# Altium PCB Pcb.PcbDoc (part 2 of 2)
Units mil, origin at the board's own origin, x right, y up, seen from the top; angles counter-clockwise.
Board outline 4875.67 x 2076.77 mil, 2 copper layers (Top Layer, Bottom Layer), stack 55.6 mil thick; 76 components, 37 nets, 162 pads, 28 vias.
Unrouted connection lines stored in the file: 67.
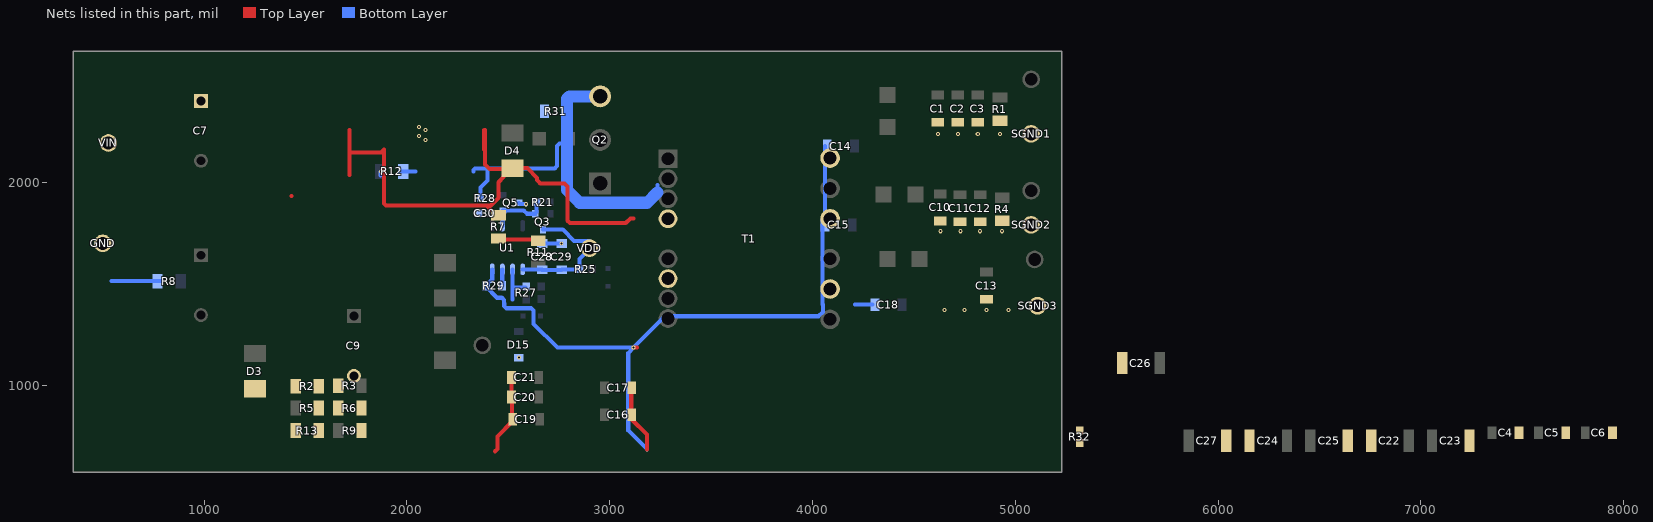
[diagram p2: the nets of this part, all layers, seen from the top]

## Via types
v1: diameter 20, hole 10, Top Layer to Bottom Layer, 28 vias

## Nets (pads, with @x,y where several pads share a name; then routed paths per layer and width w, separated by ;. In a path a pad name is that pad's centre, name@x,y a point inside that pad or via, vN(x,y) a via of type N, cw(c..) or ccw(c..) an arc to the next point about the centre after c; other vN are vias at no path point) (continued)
NetQ2_3: Q2.3 R28.2 R31.2 | length 1893.1
  Bottom Layer w20: 2327.53,2054.7 2327.53,2062.2 2335.25,2069.92 2396.32,2069.92 2728.97,2069.92 2740.69,2081.63 2740.69,2181.27 2752.4,2192.99 2778.45,2192.99 2790.1,2204.64 ; R28.2@2362.83,1923.41 2362.83,1976.56 2396.32,2010.05 2396.32,2067.95 ; 3235.04,1950.79 3235.04,1988.19
  Bottom Layer w60: Q2.3@2952.76,2425.09 2801.82,2425.09 2790.1,2413.37 2790.1,1962.53 2852.15,1900.48 3184.74,1900.48 3235.04,1950.79
NetQ3_1: Q3.1 Q5.1 R21.1 U1.6 | length 301.4
  Bottom Layer w20: U1.6@2470.73,1786.64 2470.73,1804.35 2473.29,1806.91 Q5.1@2473.29,1862.43 2576,1862.43 2592.15,1846.28 Q3.1@2633.48,1846.28 ; Q3.1@2633.48,1848.25 2639.39,1854.16 R21.1@2639.39,1903.52
NetR2_1: R2.1 R5.2
NetR6_1: R6.1 R7.2
NetR7_1: R7.1 R9.2 | length 199.9
  Top Layer w20: R7.1@2451.52,1723.88 2456.52,1718.88 2642.27,1718.88 2647.26,1713.89
NetR8_1: R8.1 R11.2 | length 244.1
  Bottom Layer w20: 542.67,1513.61 R8.1@786.77,1513.61
NetR12_1: R12.1 R13.2 | length 65
  Bottom Layer w20: R12.1@1976.38,2054.7 2041.34,2054.7
NetR27_1: R27.1 R32.2 U1.2 | length 262.3
  Bottom Layer w20: 2520.73,1481.92 R27.1@2585.1,1481.92 ; U1.2@2520.73,1572.07 2520.73,1474.21 ; 2520.73,1474.21 2520.73,1426.16 2520.73,1424.19 2520.73,1474.21
NetR29_2: R29.2 U1.3 | length 82.6
  Bottom Layer w20: R29.2@2468.17,1490.49 2470.04,1492.35 2470.04,1571.38 U1.3@2470.73,1572.07
PGND: C9.2 C22.1 C24.1 C26.1 C28.2 C29.2 C30.2 D3.2 D15.1 GND.1@500,1700 Q5.3 R13.1 R29.1 R31.1 R32.1 T1.6 U1.4 | length 3879
  Top Layer w20: 1430.29,1934.49 1431.26,1934.49 ; 3106.3,987.84 3106.3,855.41 3106.3,833.75 3183.58,756.47 3183.58,683.44 3184.06,682.97 ; v1(3118.43,1185.77) 3134.17,1185.77
  Bottom Layer w20: U1.4@2420.73,1572.07 2420.73,1521.78 2403.05,1504.11 2399.12,1504.11 2389.43,1494.42 R29.1@2389.43,1490.49 2389.43,1486.55 2444.08,1431.91 2467.74,1431.91 2479.23,1420.41 2479.23,1405.36 2479.83,1404.76 2479.83,1391.82 2491.55,1380.1 2612.8,1380.1 2624.52,1368.39 2624.52,1302.78 2741.53,1185.77 v1(3118.43,1185.77) ; Q5.3@2552.03,1899.83 2557.78,1894.08 2587.12,1894.08 v1(2588.05,1893.15) ; C28.2@2667.11,1699.44 v1(2763.13,1699.44) ; 3184.06,682.97 3184.06,685.28 3091.54,777.8 3091.54,792.56 3091.54,889.86 3091.54,987.84 3091.54,1158.88 v1(3118.43,1185.77) ; 4061.26,2180 4061.26,1802.6 4050,1791.34 4050,1398.9 4051.26,1397.64 4051.26,1362.2 4029.76,1340.71 3273.37,1340.71 v1(3118.43,1185.77)
  other v1: 2552.03,1136.32 2092.52,2209.08 2060,2229.23 2092.52,2258.27 2060,2275.02
SGND1: C1.2 C2.2 C3.2 C4.2 C5.2 C6.2 C23.2 R1.1 SGND2.1 T1.10
  other v1: 4618.38,2240 4716.81,2240 4815.23,2240 4924.75,2240
SGND2: C10.2 C11.2 C12.2 C13.2 C14.2 C15.2 C25.2 R3.1 SGND1.1 T1.12 | length 24
  Top Layer w20: C10.2@4620.62,1810.23 C10.2@4630.46,1810.23 C10.2@4632.37,1808.32 ; C11.2@4727.49,1806.4 4727.49,1804.43 C11.2@4729.45,1806.4 ; C12.2@4827.31,1806.4 C12.2@4832.08,1811.17
  other v1: 4632.37,1760 4729.45,1760 4827.31,1760 4935.58,1760
SGND3: C16.2 C17.2 C18.2 C19.2 C20.2 C21.2 C27.2 R4.1 SGND3.1 T1.14 | length 489.9
  Top Layer w20: 2435.13,674.84 2447.16,686.87 2447.16,748.34 2521.64,822.82 C19.2@2521.64,832.67 2518.91,835.4 2518.91,939.58 C20.2@2516.18,942.31 C21.2@2516.18,1039.2
  Bottom Layer w20: 4208.74,1397.64 C18.2@4296.15,1397.64
  other v1: 4652.21,1372.12 4750.63,1372.12 4858.36,1372.12 4967.07,1372.12
VDD: C28.1 C29.1 Q3.3 R25.2 U1.1 VDD.1 | length 664.9
  Bottom Layer w20: U1.1@2570.73,1572.07 2572.01,1570.8 2665.84,1570.8 C28.1@2667.11,1569.52 C29.1@2763.13,1569.52 2764.41,1570.8 2849.14,1570.8 R25.2@2850.41,1572.07 2850.41,1622.74 2900.61,1672.93 VDD.1@2900.61,1676.48 ; Q3.3@2674.32,1770.97 Q3.3@2670.89,1767.54 2768.54,1767.54 2824.95,1711.13 VDD.1@2900.61,1711.13
VIN: C7.1 D4.2 R2.2 R6.2 T1.4 VIN.1 | length 2735.7
  Top Layer w20: 1715.87,2037.04 1715.87,2147.53 ; 1715.87,2258.27 1715.87,2147.53 ; 2381.3,2260.14 2381.3,2162.3 2385.83,2157.78 ; 2385.83,2260.14 2385.83,2157.78 ; 2440.69,1838.05 2392.7,1886.05 ; D4.2@2492.62,2066.8 2407.32,2066.8 2385.83,2088.3 2385.83,2157.78 ; 3118.43,1823.56 3102.68,1823.56 3079.14,1800.02 2803.58,1800.02 2791.87,1811.74 2791.87,1980.37 2776.28,1995.96 2776.12,1995.96 2668.42,1995.96 2657.59,1995.96 2642,2011.55 2642,2022.37 2593.6,2070.77 2509.3,2070.77 2476.8,2038.27 2476.8,2026.77 2451.52,2001.49 2451.52,1924.18 2413.39,1886.05 2392.7,1886.05 ; 1715.87,2147.53 1871.05,2147.53 1885.83,2162.3 1885.83,1897.76 1897.54,1886.05 2392.7,1886.05
  Bottom Layer w20: 1870.27,2034.26 1870.27,2052.92 v1(1872.05,2054.7)
pads on no net: GND.1@2371.72,1197.49 T1.1 T1.3 T1.7 T1.8
copper on no net: | length 2532.4
  Top Layer w20: 1328.68,2147.53 1391.1,2147.53 1390.94,2147.69 1390.94,2255.18 1390.78,2255.34 ; 1505.27,2037.04 1601.7,2037.04 ; 1601.7,2147.53 1505.27,2147.53 1505.12,2147.69 1505.12,2255.18 1504.96,2255.34 1507.89,2258.27 1601.7,2258.27 ; 2520.8,2244.78 2624.83,2244.78 2652.98,2216.63 2653.38,2216.63 ; 2648.73,1323.22 2763.38,1323.22 ; 2669.53,2212.64 2668.42,2211.53 2668.42,2110.13 2776.12,2110.13 ; 2988.18,1282.93 3081.73,1282.93 3102.68,1303.88 3118.43,1303.88 3118.43,1504.67 ; 3118.43,1941.67 3118.43,2142.46 ; 4253.21,1504.67 4256.22,1504.67 ; 4253.21,1823.56 4256.22,1823.56 ; 4256.22,2142.46 4260.92,2147.16
  Bottom Layer w20: 2145.67,2054.7 2223.2,2054.7 ; 2435.13,674.84 2513.74,753.45 2513.74,807.6 2526.02,819.87 2526.02,926.91 ; 2640.19,926.91 2640.19,819.87 2646.1,813.97 2646.1,680.75 2652,674.84 ; 2966.58,682.97 2966.58,755.42 2978.29,767.13 2980.47,767.13 2991.14,777.8 2991.14,792.56 2991.14,889.86 2991.14,987.84
  other v1: 2167.32,2209.08 2197.27,2229.23 2167.32,2253.94 2196.65,2275.02

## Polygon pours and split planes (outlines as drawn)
no net on Top Layer "HV_plus" (solid, remove dead copper, pour order 17): 354.33,2598.43 777.56,2598.43 787.4,2608.27 787.4,2147.69 984.25,2147.69 984.25,2056.99 718.6,2056.99 718.5,2057.09 718.5,1934.49 358.82,1934.49 354.33,1938.98
PGND on Top Layer "Top_PGND" (solid, remove dead copper, pour order 1): 354.33,1131.65 917.55,1134.09 915.35,1958.66 2378.54,1958.66 2378.54,1909.45 3976.38,1909.45 3976.38,554.53 354.33,570.87
SGND2 on Top Layer "Sec_GND2" (solid, remove dead copper, pour order 7): 4197.44,1850.39 5230,1850.39 5230,1732.28 4197.44,1732.28
no net on Top Layer "Sec_Out2" (solid, remove dead copper, pour order 6): 4473.57,1673.23 5211.76,1673.23 5211.76,1512.57 4644.3,1534.27 4473.57,1574.8
SGND3 on Top Layer "Sec_GND3" (solid, remove dead copper, pour order 5): 4217.52,1530.6 4296.05,1531.25 4529.98,1451 5204.51,1446.77 5204.51,1338.58 4217.52,1338.58
NetC10_1 on Top Layer "Sec_Out2" (solid, remove dead copper, pour order 4): 4468.5,1998.03 5206.69,1998.03 5206.69,1899.61 4468.5,1899.61
NetC1_1 on Top Layer "Sec_Out1" (solid, remove dead copper, pour order 2): 4325.91,2627.95 5211.61,2627.95 5211.61,2390.21 4325.91,2390.21
SGND1 on Top Layer "Sec_GND1" (solid, remove dead copper, pour order 3): 4217.52,2172.24 4498.03,2214.57 4557.34,2332.37 4961.61,2332.37 5230,2321.49 5230,2113.44 4217.52,2113.44
VIN on Top Layer "HV_In" (solid, remove dead copper, pour order 0): 1340.19,2316.75 1340.51,2316.44 1340.51,1975.63 2823.11,1975.63 2823.76,1976.27 2822.38,1977.65 2822.38,2053.04 2622.16,2053.04 2584.6,2090.6 1771.26,2090.6 1766.46,2095.4 1766.46,2319.68 1343.12,2319.68
PGND on Bottom Layer "Top_PGND" (solid, remove dead copper, pour order 9): 9.84,2637.8 4090,2637.8 4090,9.84 9.84,9.84
SGND3 on Bottom Layer "Sec_GND3" (solid, remove dead copper, pour order 14): 4390,1456.69 5190,1456.69 5190,1338.58 4390,1338.58
SGND1 on Bottom Layer "Sec_GND1" (solid, remove dead copper, pour order 13): 4390,2303.15 5150,2303.15 5150,2113.44 4390,2113.44
SGND2 on Bottom Layer "Sec_GND2" (solid, remove dead copper, pour order 12): 4390,1850.39 5150,1850.39 5150,1732.28 4390,1732.28

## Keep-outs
Keep-Out Layer:
  text ".Layer_Name" at 577,-858.49 h60

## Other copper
Top Layer:
  pour cut-out: 1291.96,1973.68 1313.72,1973.68 2554.12,1973.68 2554.12,1330 1281.9,1330
  pour cut-out: 2573.68,1909.45 2573.68,1832.5 2722.27,1745.89 2745.11,1455.35 2416.09,1455.35 2416.09,1909.45
  pour cut-out: 2732.3,1940.66 2760,1750 3128.54,1682.25 3302.09,1720.36 3302.09,1936.66
  pour cut-out: 1643.7,2332.68 2868.16,2332.68 2868.16,1909.45 1634.5,1909.45
  text ".Layer_Name" at 577,-858.49 h60
Bottom Layer:
  pour cut-out: 382.96,2622.04 382.96,1122.05 836.61,1122.05 836.61,2619.27
  pour cut-out: 1690,2192.47 1690,1879.26 2432.21,1879.26 2432.21,2187.93
  pour cut-out: 2864.17,2647.64 2850.41,2633.88 2850.41,2069.92 3740,2069.92 3740,2647.64
  text ".Layer_Name" at 577,-858.49 h60

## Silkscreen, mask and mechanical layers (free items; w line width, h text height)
Top Overlay:
  text "PMP23326B" at 4644.3,610 h108.27
  text ".Layer_Name" at 577,-858.49 h60
Bottom Overlay:
  text ".Layer_Name" at 577,-858.49 h60
Top Paste:
  text ".Layer_Name" at 577,-858.49 h60
Bottom Paste:
  text ".Layer_Name" at 577,-858.49 h60
Top Solder:
  text ".Layer_Name" at 577,-858.49 h60
  text ".Layer_Name" at 577,-858.49 h60
Bottom Solder:
  text ".Layer_Name" at 577,-858.49 h60
Drill Guide:
  text ".Layer_Name" at 577,-858.49 h60
M1 Board Outline:
  lines w10: 354.33,561.02 5230,561.02 5230,1460.45 5230,1738.37 5230,2127.76 5230,2375.73 5230,2628.64 5230,2647.64 4212.6,2647.64 4049.21,2647.64 354.33,2647.64 354.33,561.02
  text ".Layer_Name" at 577,-858.49 h60
M2 Board Dimensions:
  rectangle: 0,-275 125,-150
  rectangle: 125,-400 500,-275
  lines w7: 0,-275 1000,-275 ; 125,-400 125,-150 ; 250,-400 250,-150 ; 500,-400 500,-150 ; 750,-400 750,-150 ; 0,-400 1000,-400 1000,-150 0,-150 0,-400
  text ".Layer_Name" at 577,-858.49 h60
M3 3D STEP Top:
  text ".Layer_Name" at 577,-858.49 h60
M4 3D STEP Bottom:
  text ".Layer_Name" at 577,-858.49 h60
M5 Assembly Top:
  lines w10: -292,-930.17 6308,-930.17 ; -292,-726.83 6310,-726.83 ; -292,-523.5 -292,-1133.5 3713,-1133.5 6310,-1133.5 6310,-523.5 -291.5,-523.5 -291.5,-1133.5 1284,-1133.5 ; 2173,-1133.5 2173,-523.5 ; 3440,-726.83 3440,-523.5 ; 4280,-726.83 4280,-523.5 ; 4902,-1140 4902,-937.17
  text "COMPONENTS MARKED 'DNP' SHOULD NOT BE POPULATED." at 1153.5,-318.5 h60
  text "ASSEMBLY VARIANT:" at 1153,-434 h60
  text ".VariantName" at 2189,-434 h60
  text "PCB VIEWED FROM TOP SIDE" at -228.5,-655.67 h60
  text "BOARD #:" at 2248,-655.67 h60
  text ".PRJ_Number" at 2793.5,-655.67 h60
  text "REV:" at 3638,-655.67 h60
  text ".PCB_Rev" at 3929.5,-655.67 h60
  text "SVN REV:" at 4476,-655.67 h60
  text ".VersionControl_RevNumber" at 4982,-655.67 h60
  text "TID #:" at 2248,-859 h60
  text ".TID" at 2793.5,-859 h60
  text "PLOT NAME =" at -228.5,-1064.34 h60
  text ".plot_File_Name" at 577,-1064.34 h60
  text "GENERATED    :" at 2250,-1064.34 h60
  text ".Print_Date" at 3119.5,-1064.34 h60
  text ".Print_Time" at 3848.5,-1064.34 h60
  text "TEXAS INSTRUMENTS" at 5113,-1064.34 h60
M6 Assembly Bottom:
  lines w10: -292.5,-727.33 6309.5,-727.33 ; -290.5,-930.67 6309.5,-930.67 ; 1115.5,-1140.5 1115.5,-937.67 ; 1737.5,-727.33 1737.5,-524 ; 2577.5,-727.33 2577.5,-524 ; 3844.5,-1134 3844.5,-524 ; 4733.5,-1134 6309,-1134 6309,-524 -292.5,-524 -292.5,-1134 2304.5,-1134 6309.5,-1134 6309.5,-524
  text "COMPONENTS MARKED 'DNP' SHOULD NOT BE POPULATED." at 6102,-318 h60
  text ".VariantName" at 5058,-434 h60
  text "ASSEMBLY VARIANT:" at 6097,-434 h60
  text ".VersionControl_RevNumber" at 1035.5,-656.17 h60
  text "SVN REV:" at 1541.5,-656.17 h60
  text ".PCB_Rev" at 2088,-656.17 h60
  text "REV:" at 2379.5,-656.17 h60
  text ".PRJ_Number" at 3224,-656.17 h60
  text "BOARD #:" at 3769.5,-656.17 h60
  text "PCB VIEWED FROM BOTTOM SIDE" at 6246,-656.17 h60
  text ".TID" at 3224,-859.5 h60
  text "TID #:" at 3769.5,-859.5 h60
  text "TEXAS INSTRUMENTS" at 904.5,-1064.84 h60
  text ".Print_Time" at 2169,-1064.84 h60
  text ".Print_Date" at 2898,-1064.84 h60
  text "GENERATED    :" at 3767.5,-1064.84 h60
  text ".plot_File_Name" at 5440.5,-1064.84 h60
  text "PLOT NAME =" at 6246,-1064.84 h60
M9 Title Sheet:
  drawing of 57 lines, arcs and shapes, not listed
  text "1" at 739.84,8036.5 h70
  text "2" at 3235.5,8036.5 h70
  text "3" at 5724.84,8036.5 h70
  text "4" at 8231.51,8036.5 h70
  text "5" at 10730.5,8036.5 h70
  text "6" at 13235.5,8036.5 h70
  text "A" at -416.5,6893.5 h70
  text "A" at 14383.5,6893.5 h70
  text "B" at -416.5,4513.5 h70
  text "B" at 14383.5,4513.5 h70
  text "C" at -416.5,2138.5 h70
  text "C" at 14383.5,2138.5 h70
  text "PROJECT TITLE:" at 11343.5,277.5 h45
  text ".PRJ_Title" at 11393.5,144.17 h70
  text "DESIGNED FOR:" at 11343.5,-23.5 h45
  text ".PRJ_Customer" at 11393.5,-163.5 h70
  text "D" at -416.5,-231.5 h70
  text "D" at 14383.5,-231.5 h70
  text "FILE NAME:" at 11343.5,-323.5 h45
  text ".PCB_File_Name_No_Path" at 11393.5,-443.5 h70
  text "Texas Instruments (TI) and/or its licensors do not warrant the accuracy or completeness of this specification" at 6374,-605.34 h45
  text "ENGINEER:" at 11343.5,-613.5 h45
  text "LAYOUT BY:" at 12848.5,-613.5 h45
  text "or any information contained therein. TI and/or its licensors do not warrant that this design will meet" at 6329.01,-718 h45
  text ".PRJ_Engineer" at 11393.5,-768.49 h70
  text ".PCB_Layout" at 12899,-768.49 h70
  text "the specifications, will be suitable for your application or fit for any particular purpose, or will operate in" at 6329.01,-830.67 h45
  text ".Layer_Name" at 577,-858.49 h60
  text "ALTIUM DESIGNER VERSION:" at 12848.5,-923.5 h45
  text "an implementation. TI and/or its licensors do not warrant that the design is production worthy. You should" at 6329.01,-943.33 h45
  text "completely validate and test your design implementation to confirm the system functionality for your application." at 6374,-1056 h45
  text ".print_Scale" at 11393.5,-1056.83 h70
  text ".Application_BuildNumber" at 12899,-1056.83 h70
  text "1" at 739.84,-1263.5 h70
  text "2" at 3235.5,-1263.5 h70
  text "3" at 5724.84,-1263.5 h70
  text "4" at 8231.51,-1263.5 h70
  text "5" at 10730.5,-1263.5 h70
  text "6" at 13235.5,-1263.5 h70
M10 Fab Notes:
  drawing of 189 lines, arcs and shapes, not listed
  text "DESIGN INFORMATION" at 12382.02,6356.17 h60
  text "MIN. TRACK WIDTH:" at 11737.46,6224.05 h60
  text "8" at 12833.7,6224.05 h60
  text "MIL" at 12988.46,6224.05 h60
  text "MIN. CLEARANCE:" at 11737.46,6099.92 h60
  text "0.2" at 12773.7,6099.93 h60
  text "mm" at 12988.46,6099.92 h60
  text "MIN. VIA PAD SIZE:" at 11737.46,5975.8 h60
  text "24" at 12803.71,5975.8 h60
  text "MIL" at 12988.46,5975.8 h60
  text "0.05mm (2MIL)" at 12432.46,5845.9 h60
  text "MINIMUM ANNULAR RING" at 11408.23,5837.67 h60
  text "EXTERNAL" at 13140.46,5837.67 h60
  text "PER" at 11608.23,5727.55 h60
  text "IPC-D-275 CLASS 2 LEVEL C" at 11828.23,5727.54 h60
  text "MIL, HOLES" at 13316.46,5627.07 h60
  text "+/-" at 12924,5618.48 h60
  text "+/-" at 13778,5618.48 h60
  text "REGISTRATION TOLERANCES:" at 11408.23,5617.42 h60
  text "METAL" at 12608,5617.42 h60
  text "5" at 13184.2,5617.42 h60
  text "3" at 14017.2,5617.42 h60
  text "MIL" at 14133.46,5617.42 h60
  text "HOLE SIZE TOLERANCE (UNLESS OTHERWISE SPECIFIED):" at 11408.23,5519.1 h60
  text "+/-" at 13778,5516.23 h60
  text "3" at 14017.2,5515.17 h60
  text "MIL" at 14133.46,5515.17 h60
  text "MATERIAL:" at 11333.46,5377.52 h60
  text "FR-4 High Tg" at 12319.9,5249 h60
  text "X" at 12175.46,5241.01 h60
  text "FR-408" at 11754.46,5236.49 h60
  text "OTHER" at 13242.46,5236.49 h60
  text "62 MIL (1.6mm) +/-10%" at 12074.56,5093.46 h60
  text "X" at 11954.46,5091.01 h60
  text "THICKNESS:" at 11408.23,5085.24 h60
  text "OTHER" at 13359.46,5085.24 h60
  text "TOLERANCE:" at 11408.23,4946.92 h60
  text "X" at 12256.46,4946.92 h60
  text "ANSI IPC-6012 TYPE 3 CLASS 2" at 12434.48,4946.92 h60
  text "OTHER +/-" at 12434.46,4802.73 h60
  text "BOW & TWIST:" at 11408.23,4657.54 h60
  text "X" at 12256.46,4657.54 h60
  text "ANSI IPC-6012 TYPE 3 CLASS 2" at 12434.48,4657.54 h60
  text "OTHER +/-" at 12434.46,4510.85 h60
  text "DRILLING:" at 11333.46,4380.23 h60
  text "NC_DRILL FILES" at 13094.46,4275.04 h60
  text "REFERENCE:" at 11408.23,4271.1 h60
  text "X" at 12065.46,4271.01 h60
  text "AS SHOWN" at 12243.46,4271.1 h60
  text "X" at 12966.46,4271.1 h60
  text "OTHER" at 13392.46,4128.85 h60
  text "PTH COPPER THICKNESS:" at 11407.91,4125.32 h60
  text "X" at 12547.14,4125.32 h60
  text "20-30 um" at 12675.14,4125.32 h60
  text "BOARD FINISH:" at 11333.46,3977.73 h60
  text "SILKSCREEN:" at 11488.68,3867.6 h60
  text "X" at 12446.46,3867.6 h60
  text "TOP" at 12563.46,3867.6 h60
  text "X" at 12956.46,3867.6 h60
  text "BOTTOM" at 13074.46,3867.6 h60
  text "SILKSCREEN COLOR:" at 11488.68,3712.41 h60
  text "X" at 12445.46,3712.41 h60
  text "WHITE" at 12563.46,3712.41 h60
  text "OTHER" at 13074.46,3712.41 h60
  text "X" at 12576.46,3568.96 h60
  text "GREEN" at 12694.46,3568.96 h60
  text "OTHER" at 13312.46,3568.96 h60
  text "SOLDER RESIST COLOR:" at 11488.68,3562.1 h60
  text "X" at 12576.46,3414.71 h60
  text "MATTE" at 12694.46,3414.71 h60
  text "SEMI-GLOSS" at 13312,3414.07 h60
  text "IMMERSION GOLD (ENIG)" at 12394.46,3241.94 h60
  text "ENEPIG" at 13732,3234.72 h60
  text "SURFACE FINISH:" at 11333.46,3233.72 h60
  text "X" at 11515.75,3096.4 h60
  text "IMM. TIN/SILVER OR EQUIV" at 11663,3096.4 h60
  text "OTHER" at 13094.46,3092.47 h60
  text "ARRAY/PANEL:" at 11333.46,2937.09 h60
  text "X" at 12224.41,2937.09 h60
  text "CUT AND TRIM PER M1 BOARD OUTLINE" at 12394.46,2928.87 h60
  text "N.C. ROUTE" at 12394.46,2792.9 h60
  text "V. SCORE" at 13260.46,2792.9 h60
  text "CERTIFICATION:" at 11333.46,2663.77 h60
  text "MATERIALS AND WORKMANSHIP FOR ALL PCBS" at 12058.46,2663.77 h60
  text "TO MEET OR EXCEED THE REQUIREMENTS OF:" at 12058.46,2569.71 h60
  text "X" at 11695.97,2441.08 h60
  text "ANSI IPC-A-600F CLASS ->" at 11823.96,2441.08 h60
  text "X" at 13471.97,2441.08 h60
  text "2" at 13581.96,2441.08 h60
  text "1" at 13266.96,2439.58 h60
  text "3" at 13935.96,2439.58 h60
  text "X" at 12507.97,2293.39 h60
  text "RoHS" at 12635.96,2293.39 h60
  text "OTHER" at 13280.36,2293.39 h60
  text "PER ORDER" at 13677.42,2293.39 h60
  text "ALL BOARDS MUST MEET OR EXCEED UL94-V0 REQUIREMENTS." at 11361,2139.57 h60
  text "PCB MUST BEAR THE UL94V-0 UL REGISTERED MATERIAL ID NUMBER" at 11361,2023.5 h60
  text "ADDITIONAL REQUIREMENTS:" at 11333.46,1854.08 h60
  text "MICROSECTION:" at 11408.23,1746.95 h60
  text "YES" at 12313.96,1746.95 h60
  text "REQUIRED" at 13175.46,1602.62 h60
  text "BARE BOARD ELEC. TEST:" at 11408.23,1599.76 h60
  text "NONE" at 12713.96,1599.76 h60
  text "X" at 13057.46,1599.76 h60
  text "PER ORDER" at 13767.46,1599.76 h60
  text "XX MIL VIAS REQUIRE NON-CONDUCTIVE FILL AND PLANARIZE" at 11576.38,1394.82 h59
  text "XX MIL VIAS REQUIRE CONDUCTIVE FILL AND PLANARIZE" at 11584.38,1290.84 h60
  text "OUTER XX MIL TRACES REQUIRE 50 OHM SINGLE-ENDED IMPEDANCE" at 11583.39,1127.46 h58
  text "LAYER 2 & 3 (INNER LAYERS) XX MIL WIDE, XX MIL SPACE / TRACES REQUIRE 100 OHM DIFFERENTIAL IMPEDANCE" at 11575.39,891.74 h60
  text ".Layer_Name" at 577,-858.49 h60
M11 Gerber Information:
  lines w10: -292,-930.17 6308,-930.17 ; -292,-726.83 6310,-726.83 ; -292,-523.5 -292,-1133.5 3713,-1133.5 6310,-1133.5 6310,-523.5 -291.5,-523.5 -291.5,-1133.5 1284,-1133.5 ; 2173,-1133.5 2173,-523.5 ; 3440,-726.83 3440,-523.5 ; 4280,-726.83 4280,-523.5 ; 4902,-1140 4902,-937.17
  text "ALL ARTWORK VIEWED FROM TOP SIDE" at -228.5,-655.67 h60
  text "BOARD #:" at 2248,-655.67 h60
  text ".PRJ_Number" at 2793.5,-655.67 h60
  text "REV:" at 3638,-655.67 h60
  text ".PCB_Rev" at 3929.5,-655.67 h60
  text "SVN REV:" at 4476,-655.67 h60
  text ".VersionControl_RevNumber" at 4982,-655.67 h60
  text "LAYER NAME =" at -228.5,-858.49 h60
  text "TID #:" at 2248,-859 h60
  text ".TID" at 2793.5,-859 h60
  text "PLOT NAME =" at -228.5,-1064.34 h60
  text ".plot_File_Name" at 577,-1064.34 h60
  text "GENERATED    :" at 2250,-1064.34 h60
  text ".Print_Date" at 3119.5,-1064.34 h60
  text ".Print_Time" at 3848.5,-1064.34 h60
  text "TEXAS INSTRUMENTS" at 5113,-1064.34 h60
M12 Stackup:
  drawing of 162 lines, arcs and shapes, not listed
  text "Layer" at 9797.84,7762.5 h60
  text "Name" at 10048.93,7762.5 h60
  text "Material" at 10534.51,7762.5 h60
  text "Thickness" at 10970.86,7762.5 h60
  text "Constant" at 11329.29,7762.5 h60
  text "Board Layer Stack" at 11661.02,7762.5 h60
  text "Top Overlay" at 10048.93,7642.5 h60
  text "Top Solder" at 10048.93,7522.5 h60
  text "Solder Resist" at 10534.51,7522.5 h60
  text "0.40mil" at 10970.86,7522.5 h60
  text "3.5" at 11329.29,7522.5 h60
  text "1" at 9797.84,7402.5 h60
  text "Top Layer" at 10048.93,7402.5 h60
  text "2.80mil" at 10970.81,7402.5 h60
  text "Dielectric 1" at 10048.93,7282.5 h60
  text "FR-4" at 10534.51,7282.5 h60
  text "14.20mil" at 10970.86,7282.5 h60
  text "4.8" at 11329.29,7282.5 h60
  text "Dielectric1" at 10048.93,7162.5 h60
  text "21.60mil" at 10970.81,7162.5 h60
  text "4.2" at 11329.29,7162.5 h60
  text "Dielectric 2" at 10048.93,7042.5 h60
  text "FR-4" at 10534.51,7042.5 h60
  text "14.20mil" at 10970.86,7042.5 h60
  text "4.8" at 11329.29,7042.5 h60
  text "2" at 9797.79,6922.5 h60
  text "Bottom Layer" at 10048.93,6922.5 h60
  text "2.80mil" at 10970.81,6922.5 h60
  text "Bottom Solder" at 10048.93,6802.5 h60
  text "Solder Resist" at 10534.51,6802.5 h60
  text "0.40mil" at 10970.86,6802.5 h60
  text "3.5" at 11329.29,6802.5 h60
  text "Bottom Overlay" at 10048.93,6682.5 h60
  text ".Layer_Name" at 577,-858.49 h60
M13 Component Bodies Top:
  text ".Layer_Name" at 577,-858.49 h60
M14 Component Bodies Bottom:
  text ".Layer_Name" at 577,-858.49 h60
M15 Courtyards Top:
  text ".Layer_Name" at 577,-858.49 h60
M16 Courtyards Bottom:
  text ".Layer_Name" at 577,-858.49 h60
Drill Drawing:
  lines w10: 7544.59,3156.7 7599.84,3156.7 7572.22,3101.45 7544.59,3156.7 ; 7544.59,3225.77 7599.84,3225.77 7599.84,3281.02 7544.59,3281.02 7544.59,3225.77 ; 7544.59,3363.9 7558.4,3363.9 7572.22,3350.09 7586.03,3363.9 7599.84,3363.9 7586.03,3377.72 7599.84,3391.53 7586.03,3391.53 7572.22,3405.34 7558.4,3391.53 7544.59,3391.53 7558.4,3377.72 7544.59,3363.9 ; 7544.59,3488.22 7558.4,3488.22 7558.4,3474.41 7586.03,3474.41 7586.03,3488.22 7599.84,3488.22 7599.84,3515.85 7586.03,3515.85 7586.03,3529.66 7558.4,3529.66 7558.4,3515.85 7544.59,3515.85 7544.59,3488.22 ; 7544.59,3598.73 7572.22,3612.54 7599.84,3598.73 7586.03,3626.36 7599.84,3653.98 7572.22,3640.17 7544.59,3653.98 7558.4,3626.36 7544.59,3598.73
  lines w12: 7494.5,3064.15 10725.99,3064.15 ; 7494.5,3685.75 10725.99,3685.75 ; 7832.36,2939.83 7832.36,3810.07 ; 8164.36,2939.83 8164.36,3810.07 ; 8800.93,2939.83 8800.93,3810.07 ; 9060.07,2939.83 9060.07,3810.07 ; 9435.22,2939.83 9435.22,3810.07 ; 10159.55,2939.83 10159.55,3810.07 ; 7494.5,2939.83 10725.99,2939.83 10725.99,3810.07 7494.5,3810.07 7494.5,2939.83
  text "Symbol" at 7569.09,3723.05 h72
  text "Quantity" at 7869.66,3723.05 h72
  text "Finished Hole Size" at 8201.66,3723.05 h72
  text "Plated" at 8838.22,3723.05 h72
  text "Hole Type" at 9097.36,3723.05 h72
  text "Drill Layer Pair" at 9472.52,3723.05 h72
  text "Hole Tolerance" at 10196.85,3723.05 h72
  text "28" at 7869.66,3598.73 h60
  text "10.00mil (0.254mm)" at 8201.66,3598.73 h60
  text "PTH" at 8838.22,3598.73 h60
  text "Round" at 9097.36,3598.73 h60
  text "Top Layer - Bottom Layer" at 9472.52,3598.73 h60
  text "6" at 7869.66,3474.41 h60
  text "43.31mil (1.100mm)" at 8201.66,3474.41 h60
  text "PTH" at 8838.22,3474.41 h60
  text "Round" at 9097.36,3474.41 h60
  text "Top Layer - Bottom Layer" at 9472.52,3474.41 h60
  text "14" at 7869.66,3350.09 h60
  text "62.99mil (1.600mm)" at 8201.66,3350.09 h60
  text "PTH" at 8838.22,3350.09 h60
  text "Round" at 9097.36,3350.09 h60
  text "Top Layer - Bottom Layer" at 9472.52,3350.09 h60
  text "10" at 7869.66,3225.77 h60
  text "63.00mil (1.600mm)" at 8201.66,3225.77 h60
  text "PTH" at 8838.22,3225.77 h60
  text "Round" at 9097.36,3225.77 h60
  text "Top Layer - Bottom Layer" at 9472.52,3225.77 h60
  text "3" at 7869.66,3101.45 h60
  text "70.87mil (1.800mm)" at 8201.66,3101.45 h60
  text "PTH" at 8838.22,3101.45 h60
  text "Round" at 9097.36,3101.45 h60
  text "Top Layer - Bottom Layer" at 9472.52,3101.45 h60
  text "61 Total" at 7869.66,2977.13 h60
  text ".Layer_Name" at 577,-858.49 h60
M17 Embedded Cavity:
  text ".Layer_Name" at 577,-858.49 h60
M18 Embedded Assembly:
  text ".Layer_Name" at 577,-858.49 h60
M19 Embedded Keepout:
  text ".Layer_Name" at 577,-858.49 h60

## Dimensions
0,-400 to 1000,-400 on M2 Board Dimensions
354.33,561.02 to 354.33,2647.64 on M2 Board Dimensions
354.33,561.02 to 5230,570.87 on M2 Board Dimensions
